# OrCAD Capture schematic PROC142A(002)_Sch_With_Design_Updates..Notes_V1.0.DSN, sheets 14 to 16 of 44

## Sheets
14 13. CURRENT MONITORING DEVICES: size C; title: CURRENT MONITORING DEVICES
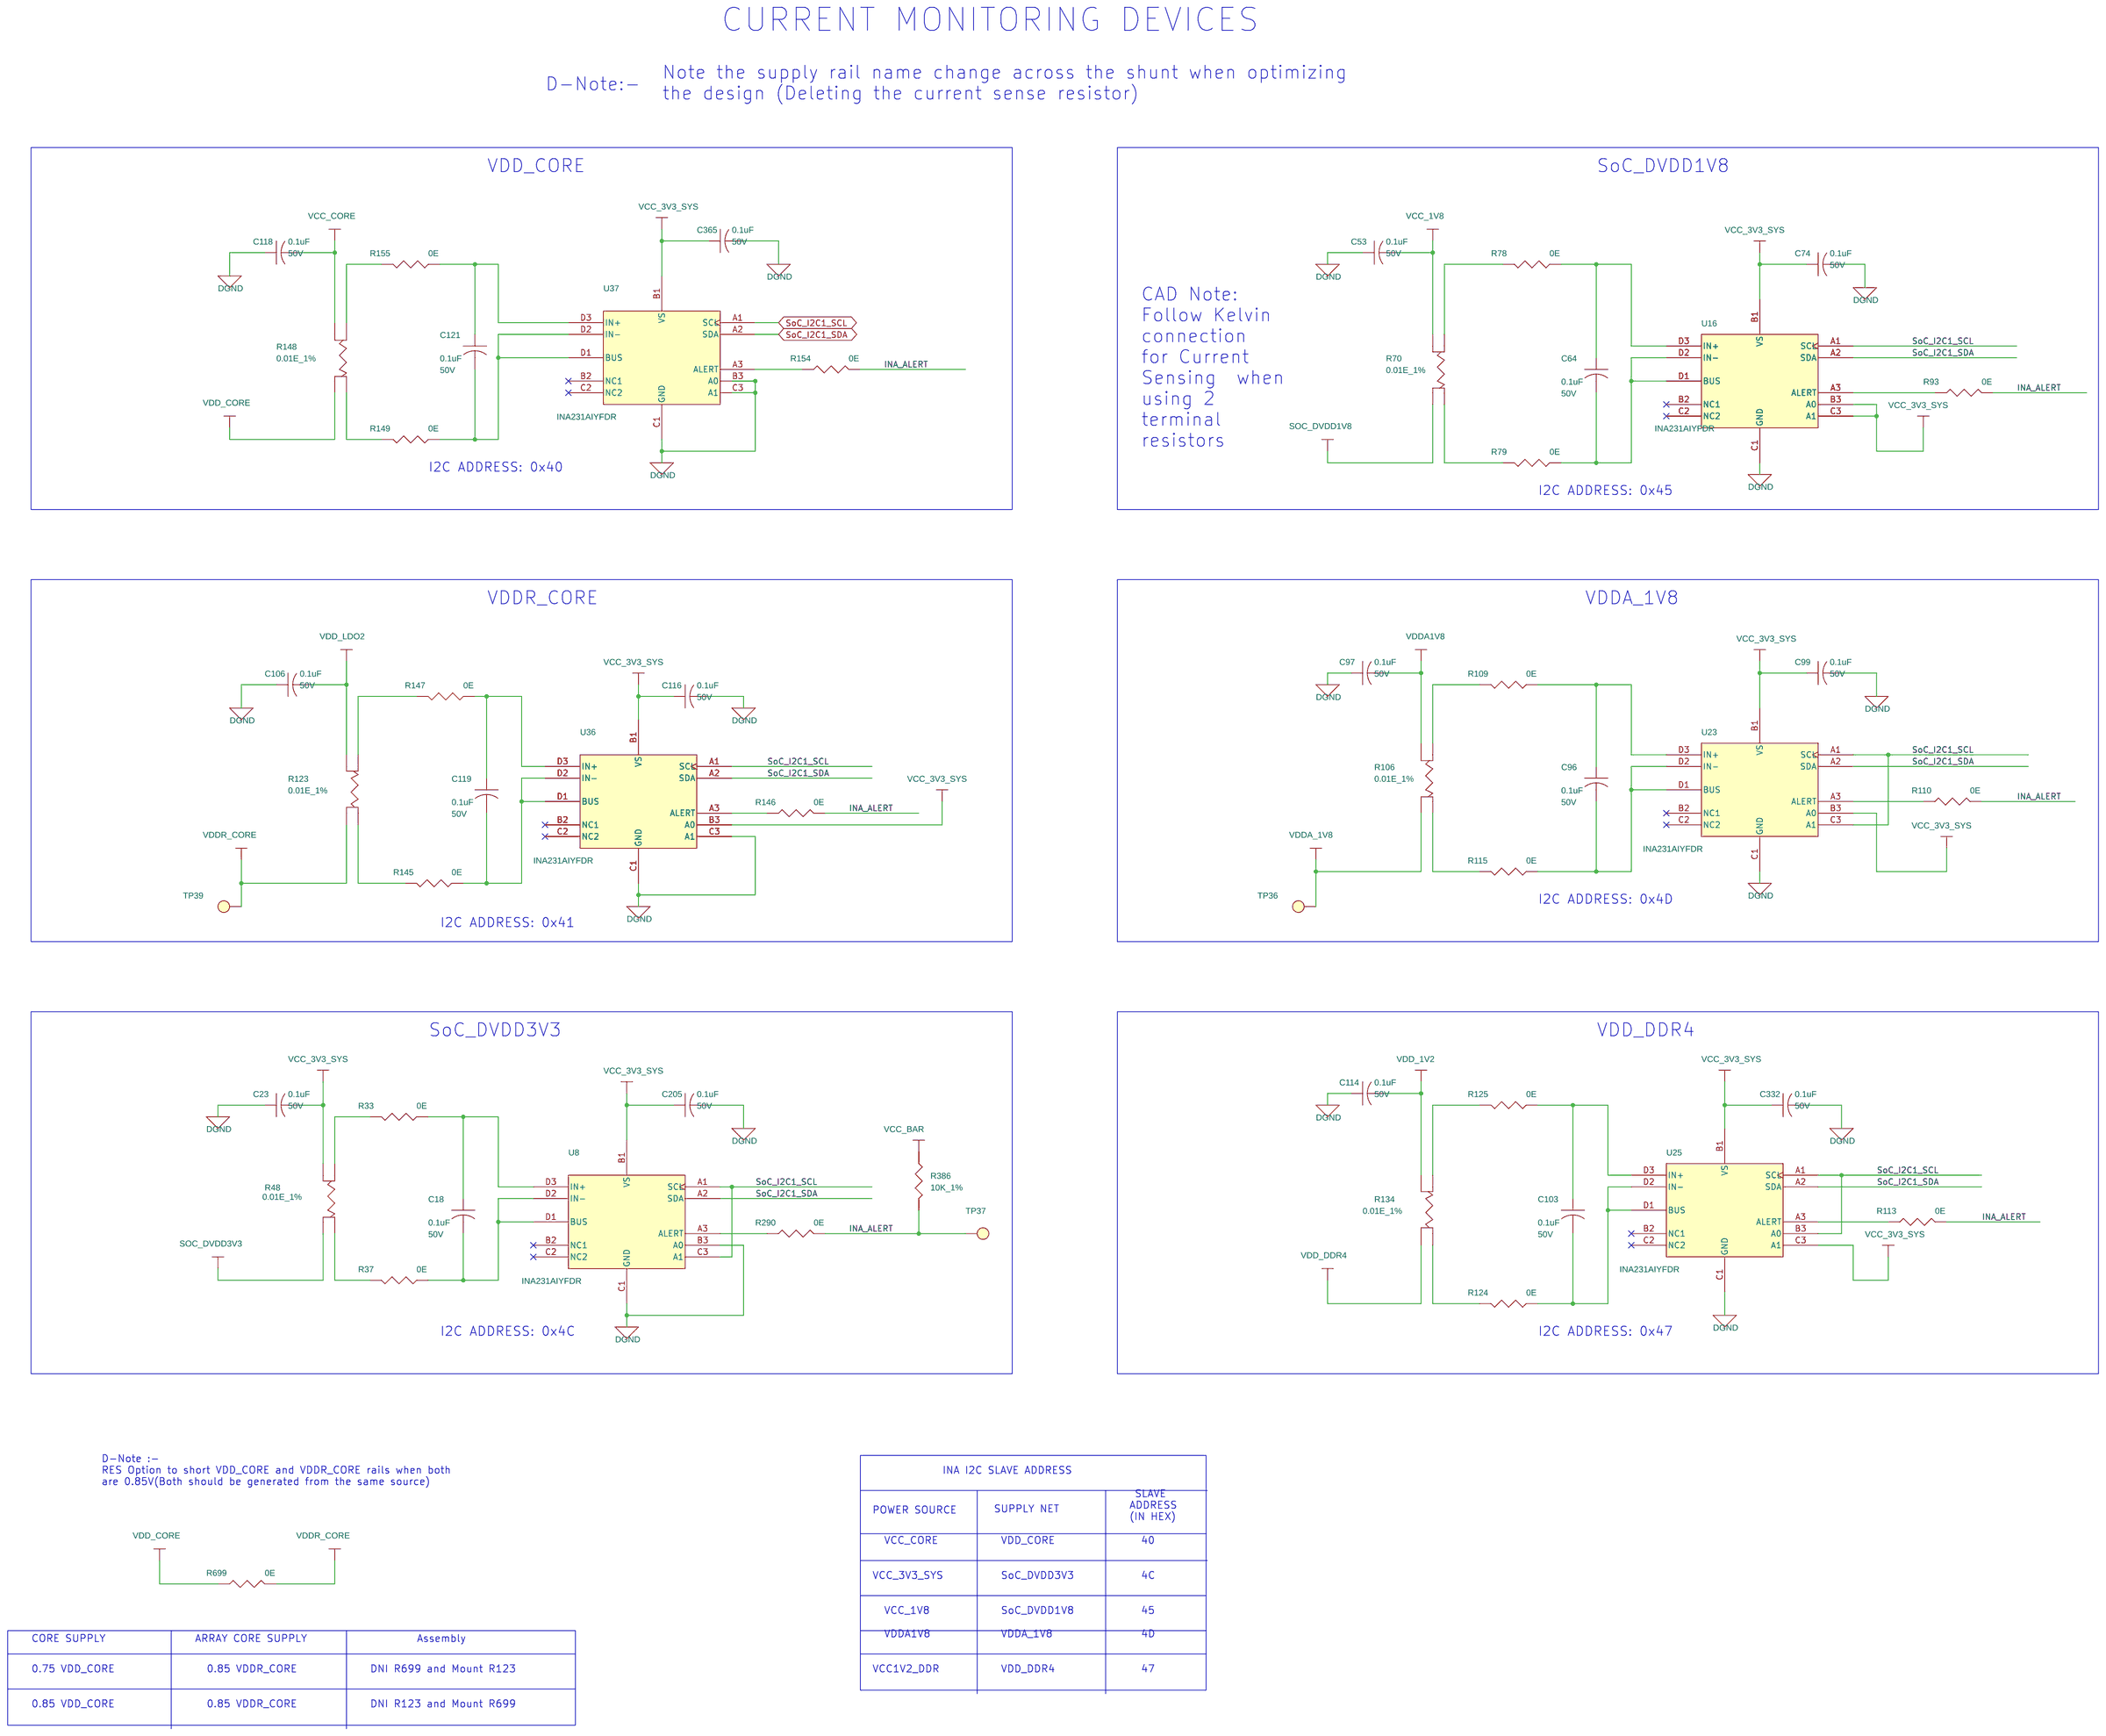
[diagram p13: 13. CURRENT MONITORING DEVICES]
15 14. SOC POWER: size C; title: SOC POWER
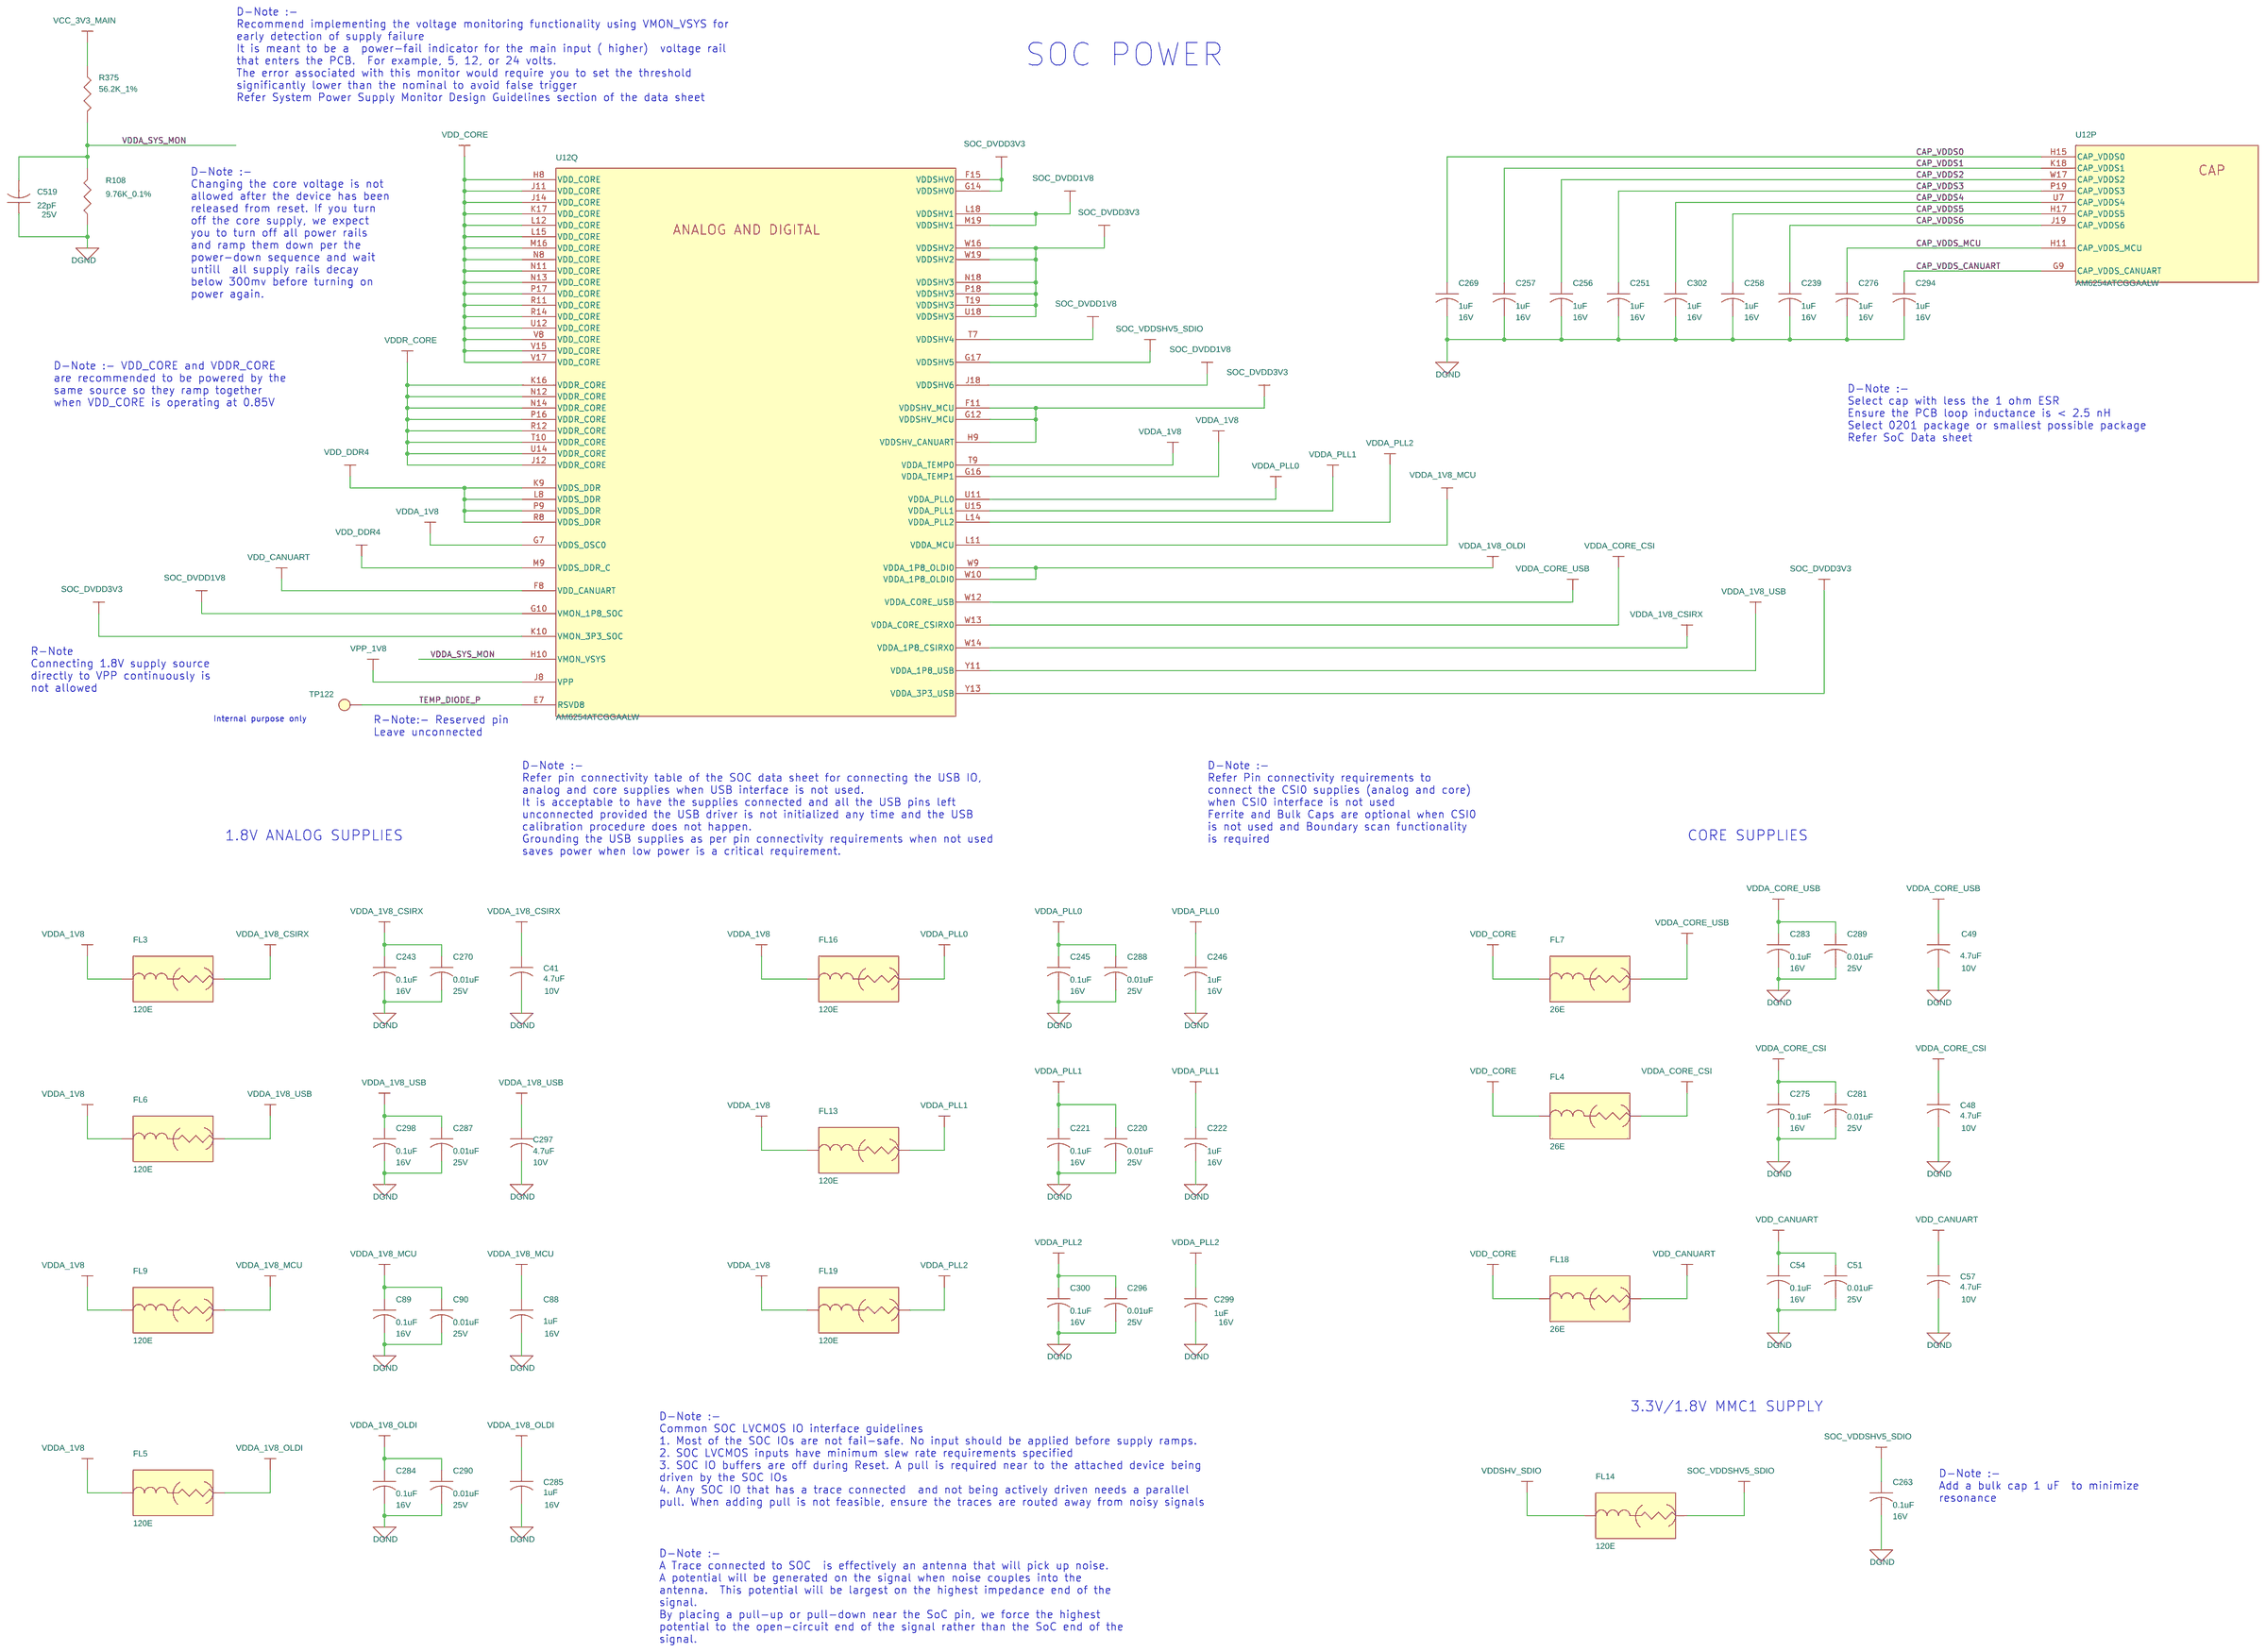
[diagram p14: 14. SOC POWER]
16 15. SOC POWER CAPS: size C; title: SOC POWER CAPS & SOC VSS
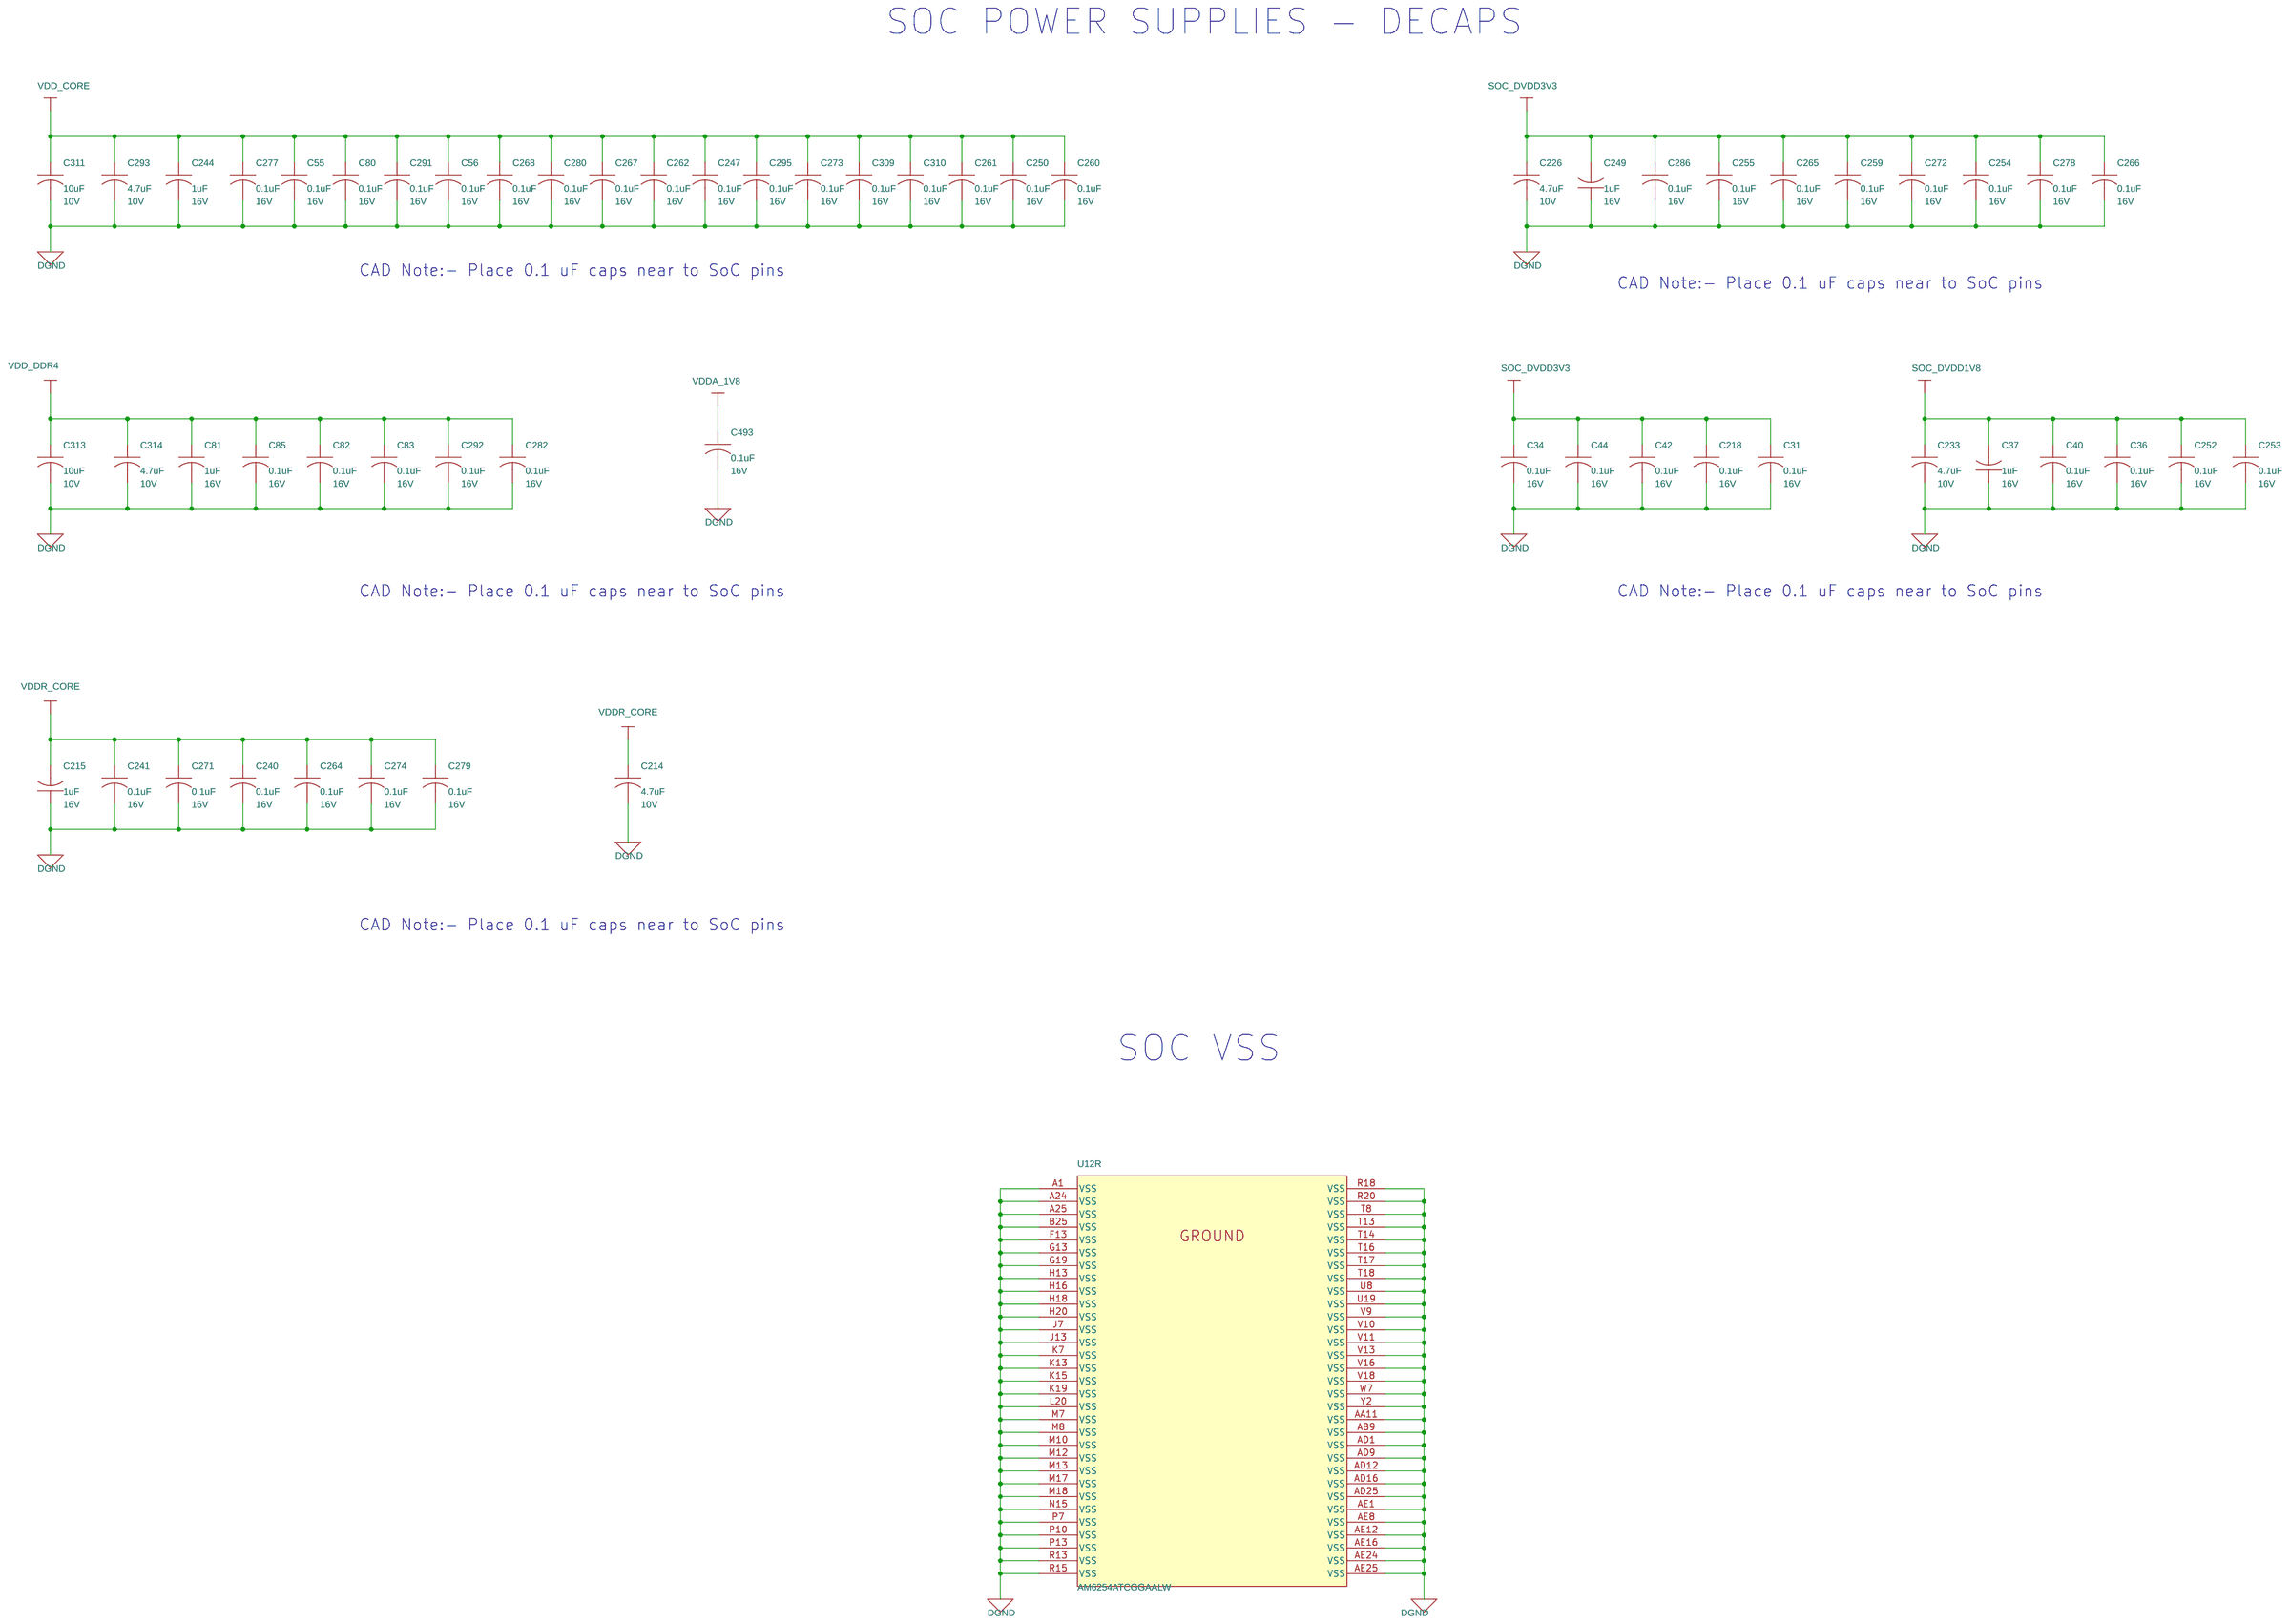
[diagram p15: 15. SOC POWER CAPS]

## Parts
sheet 13. CURRENT MONITORING DEVICES
C18  0.1uF  [CAP0402_0-75]
C23  0.1uF  [CAP0402_0-75]
C53  0.1uF  [CAP0402_0-75]
C64  0.1uF  [CAP0402_0-75]
C74  0.1uF  [CAP0402_0-75]
C96  0.1uF  [CAP0402_0-75]
C97  0.1uF  [CAP0402_0-75]
C99  0.1uF  [CAP0402_0-75]
C103  0.1uF  [CAP0402_0-75]
C106  0.1uF  [CAP0402_0-75]
C114  0.1uF  [CAP0402_0-75]
C116  0.1uF  [CAP0402_0-75]
C118  0.1uF  [CAP0402_0-75]
C119  0.1uF  [CAP0402_0-75]
C121  0.1uF  [CAP0402_0-75]
C205  0.1uF  [CAP0402_0-75]
C332  0.1uF  [CAP0402_0-75]
C365  0.1uF  [CAP0402_0-75]
R33  0E  [RES0402_0-5]
R37  0E  [RES0402_0-5]
R48  0.01E_1%  [RES_KRL3216T4_1206-4_0-7]
R70  0.01E_1%  [RES_KRL3216T4_1206-4_0-7]
R78  0E  [RES0402_0-5]
R79  0E  [RES0402_0-5]
R93  0E  [RES0402_0-5]
R106  0.01E_1%  [RES_KRL3216T4_1206-4_0-7]
R109  0E  [RES0402_0-5]
R110  0E  [RES0402_0-5]
R113  0E  [RES0402_0-5]
R115  0E  [RES0402_0-5]
R123  0.01E_1%  [RES_KRL3216T4_1206-4_0-7]
R124  0E  [RES0402_0-5]
R125  0E  [RES0402_0-5]
R134  0.01E_1%  [RES_KRL3216T4_1206-4_0-7]
R145  0E  [RES0402_0-5]
R146  0E  [RES0402_0-5]
R147  0E  [RES0402_0-5]
R148  0.01E_1%  [RES_KRL3216T4_1206-4_0-7]
R149  0E  [RES0402_0-5]
R154  0E  [RES0402_0-5]
R155  0E  [RES0402_0-5]
R290  0E  [RES0402_0-5]
R386  10K_1%  [RES0201_0-5]
R699  0E  [RES0805_0-75]
TP36  TP20_SMD  [TP20_SMD]
TP37  TP20_SMD  [TP20_SMD]
TP39  TP20_SMD  [TP20_SMD]
U8  INA231AIYFDR  [DSBGA12_15-74_60X70_0-4]
U16  INA231AIYFDR  [DSBGA12_15-74_60X70_0-4]
U23  INA231AIYFDR  [DSBGA12_15-74_60X70_0-4]
U25  INA231AIYFDR  [DSBGA12_15-74_60X70_0-4]
U36  INA231AIYFDR  [DSBGA12_15-74_60X70_0-4]
U37  INA231AIYFDR  [DSBGA12_15-74_60X70_0-4]
sheet 14. SOC POWER
C41  4.7uF  [CAP0402_0-75]
C48  4.7uF  [CAP0402_0-75]
C49  4.7uF  [CAP0402_0-75]
C51  0.01uF  [CAP0201_0-5]
C54  0.1uF  [CAP0201_0-5]
C57  4.7uF  [CAP0402_0-75]
C88  1uF  [CAP0201_0-5]
C89  0.1uF  [CAP0201_0-5]
C90  0.01uF  [CAP0201_0-5]
C220  0.01uF  [CAP0201_0-5]
C221  0.1uF  [CAP0201_0-5]
C222  1uF  [CAP0201_0-5]
C239  1uF  [CAP0201_0-5]
C243  0.1uF  [CAP0201_0-5]
C245  0.1uF  [CAP0201_0-5]
C246  1uF  [CAP0201_0-5]
C251  1uF  [CAP0201_0-5]
C256  1uF  [CAP0201_0-5]
C257  1uF  [CAP0201_0-5]
C258  1uF  [CAP0201_0-5]
C263  0.1uF  [CAP0201_0-5]
C269  1uF  [CAP0201_0-5]
C270  0.01uF  [CAP0201_0-5]
C275  0.1uF  [CAP0201_0-5]
C276  1uF  [CAP0201_0-5]
C281  0.01uF  [CAP0201_0-5]
C283  0.1uF  [CAP0201_0-5]
C284  0.1uF  [CAP0201_0-5]
C285  1uF  [CAP0201_0-5]
C287  0.01uF  [CAP0201_0-5]
C288  0.01uF  [CAP0201_0-5]
C289  0.01uF  [CAP0201_0-5]
C290  0.01uF  [CAP0201_0-5]
C294  1uF  [CAP0201_0-5]
C296  0.01uF  [CAP0201_0-5]
C297  4.7uF  [CAP0402_0-75]
C298  0.1uF  [CAP0201_0-5]
C299  1uF  [CAP0201_0-5]
C300  0.1uF  [CAP0201_0-5]
C302  1uF  [CAP0201_0-5]
C519  22pF  [CAP0201_0-5]
FL3  120E  [EMIFIL_BLM15A_0402_0-6]
FL4  26E  [EMIFIL_BLM18K_0603_0-7]
FL5  120E  [EMIFIL_BLM15A_0402_0-6]
FL6  120E  [EMIFIL_BLM15A_0402_0-6]
FL7  26E  [EMIFIL_BLM18K_0603_0-7]
FL9  120E  [EMIFIL_BLM15A_0402_0-6]
FL13  120E  [EMIFIL_BLM15A_0402_0-6]
FL14  120E  [EMIFIL_BLM15A_0402_0-6]
FL16  120E  [EMIFIL_BLM15A_0402_0-6]
FL18  26E  [EMIFIL_BLM18K_0603_0-7]
FL19  120E  [EMIFIL_BLM15A_0402_0-6]
R108  9.76K_0.1%  [RES0402_0-5]
R375  56.2K_1%  [RES0402_0-5]
TP122  TP20_SMD  [TP20_SMD]
sheet 15. SOC POWER CAPS
C31  0.1uF  [CAP0201_0-5]
C34  0.1uF  [CAP0201_0-5]
C36  0.1uF  [CAP0201_0-5]
C37  1uF  [CAP0201_0-5]
C40  0.1uF  [CAP0201_0-5]
C42  0.1uF  [CAP0201_0-5]
C44  0.1uF  [CAP0201_0-5]
C55  0.1uF  [CAP0201_0-5]
C56  0.1uF  [CAP0201_0-5]
C80  0.1uF  [CAP0201_0-5]
C81  1uF  [CAP0201_0-5]
C82  0.1uF  [CAP0201_0-5]
C83  0.1uF  [CAP0201_0-5]
C85  0.1uF  [CAP0201_0-5]
C214  4.7uF  [CAP0402_0-75]
C215  1uF  [CAP0201_0-5]
C218  0.1uF  [CAP0201_0-5]
C226  4.7uF  [CAP0402_0-75]
C233  4.7uF  [CAP0402_0-75]
C240  0.1uF  [CAP0201_0-5]
C241  0.1uF  [CAP0201_0-5]
C244  1uF  [CAP0201_0-5]
C247  0.1uF  [CAP0201_0-5]
C249  1uF  [CAP0201_0-5]
C250  0.1uF  [CAP0201_0-5]
C252  0.1uF  [CAP0201_0-5]
C253  0.1uF  [CAP0201_0-5]
C254  0.1uF  [CAP0201_0-5]
C255  0.1uF  [CAP0201_0-5]
C259  0.1uF  [CAP0201_0-5]
C260  0.1uF  [CAP0201_0-5]
C261  0.1uF  [CAP0201_0-5]
C262  0.1uF  [CAP0201_0-5]
C264  0.1uF  [CAP0201_0-5]
C265  0.1uF  [CAP0201_0-5]
C266  0.1uF  [CAP0201_0-5]
C267  0.1uF  [CAP0201_0-5]
C268  0.1uF  [CAP0201_0-5]
C271  0.1uF  [CAP0201_0-5]
C272  0.1uF  [CAP0201_0-5]
C273  0.1uF  [CAP0201_0-5]
C274  0.1uF  [CAP0201_0-5]
C277  0.1uF  [CAP0201_0-5]
C278  0.1uF  [CAP0201_0-5]
C279  0.1uF  [CAP0201_0-5]
C280  0.1uF  [CAP0201_0-5]
C282  0.1uF  [CAP0201_0-5]
C286  0.1uF  [CAP0201_0-5]
C291  0.1uF  [CAP0201_0-5]
C292  0.1uF  [CAP0201_0-5]
C293  4.7uF  [CAP0402_0-75]
C295  0.1uF  [CAP0201_0-5]
C309  0.1uF  [CAP0201_0-5]
C310  0.1uF  [CAP0201_0-5]
C311  10uF  [CAP0402_0-75]
C313  10uF  [CAP0402_0-75]
C314  4.7uF  [CAP0402_0-75]
C493  0.1uF  [CAP0201_0-5]
sheet 42. OSCILLATOR
U12  AM6254ATCGGAALW  [BGA425_19-68_510X510_0-7]  (sections A,B,C,D,E,F,G,H,I,J,K,L,M,N,O,P,Q,R)

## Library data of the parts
C18 C23 C53 C64 C74 C96 C97 C99 C103 C106 C114 C116 C118 C119 C121 C205 C332 C365 = CAP: CAP CERAMIC 0.1uF 50V 10% X7R 0402; Alt_Mfr_name: YAGEO AMERICA; Alt_Mfr_part_number: CC0402KRX5R8BB104; Chkd/date: MANIRAJA/261020; Crtd /date: ALVY/211020; Custom_Duty: 15%; Customs_HS_Code: 85322990; Distributor_name: DIGIKEY; Distributor_part_number: 490-10700-1-ND; Footprint Path: Y:\MIS_DATABASE\Library\ALTIUM_TOOL\PCB_FOOTPRINTS\Altium_Footprint_Lib.PcbLib; Height: 0.55MM; Library Path: Y:\MIS_DATABASE\Library\ALTIUM_TOOL\SCHEMATICS_PARTS\MS_DISCRETE_Library.schlib; Mfr_name: MURATA; Mfr_part_number: GRM155R71H104KE14D; Mistral Part No: 120011100014-R; Package: 0402; Part_type: CAPACITORS\CERAMIC; Project: J7_CP; RoHS: RoHS; Temperature: -55°C+125°C; Tolerance: 10%; Voltage: 50V; Wattage: NA; Weight: 3.1mg; Datasheet: Y:\MIS_DATABASE\DATASHEETS\CAPACITORS\GRM155R71H104KE14.PDF
R33 R37 R78 R79 R93 R109 R110 R113 R115 R124 R125 R145-R147 R149 R154 R155 R290 = RESISTOR: RES 0E 1/16W JUMPER 0402; Chkd/date: VASANTHA/201216; Crtd /date: MUDDU/190810; Custom_Duty: 15%; Customs_HS_Code: 85332119; Distributor_name: DIGIKEY; Distributor_part_number: 541-0.0JCT-ND; Footprint Path: Y:\MIS_DATABASE\Library\ALTIUM_TOOL\PCB_FOOTPRINTS\Altium_Footprint_Lib.PcbLib; Height: 0.40MM; Library Path: Y:\MIS_DATABASE\Library\ALTIUM_TOOL\SCHEMATICS_PARTS\MS_DISCRETE_Library.schlib; Mfr_name: VISHAY; Mfr_part_number: CRCW04020000Z0ED; Mistral Part No: 110010080019-R; Package: 0402; Part_type: RESISTORS\FIXED; Project: PB_BUGBASE; RoHS: RoHS; Temperature: -55°C+155°C; Tolerance: NA; Voltage: NA; Wattage: 1/16W; Weight: 0.65mg; Datasheet: Y:\MIS_DATABASE\DATASHEETS\RESISTORS\CRCW0603.PDF
R48 R70 R106 R123 R134 R148 = RESISTOR-4TERM: RES 0.01E 1W 1% 1206-4; Chkd/date: MANIRAJA/060318; Crtd /date: MANIRAJA/060318; Custom_Duty: 15%; Customs_HS_Code: 85332119; Distributor_name: DIGIKEY; Distributor_part_number: 408-1974-1-ND; Footprint Path: Y:\MIS_DATABASE\Library\ALTIUM_TOOL\PCB_FOOTPRINTS\Altium_Footprint_Lib.PcbLib; Height: 0.70MM; Library Path: Y:\MIS_DATABASE\Library\ALTIUM_TOOL\SCHEMATICS_PARTS\MS_DISCRETE_Library.schlib; Mfr_name: SUSUMU; Mfr_part_number: KRL3216T4A-M-R010-F-T1; Mistral Part No: 110018030003-R; Package: 1206-4; Part_type: RESISTORS\FIXED; Project: GRACO SMART MODULE; RoHS: RoHS; Temperature: -55°C+155°C; Tolerance: 1%; Voltage: NA; Wattage: 1W; Weight: 16.2mg; Datasheet: Y:\MIS_DATABASE\DATASHEETS\RESISTORS\KRL-SERIES.PDF
R386 = RESISTOR: RES 10K 1/20W 1% 0201; Chkd/date: VASANTHA/270117; Crtd /date: MANIRAJA/270117; Custom_Duty: 15%; Customs_HS_Code: 85332119; Distributor_name: DIGIKEY; Distributor_part_number: 311-10.0KMCT-ND; Footprint Path: Y:\MIS_DATABASE\Library\ALTIUM_TOOL\PCB_FOOTPRINTS\Altium_Footprint_Lib.PcbLib; Height: 0.26MM; Library Path: Y:\MIS_DATABASE\Library\ALTIUM_TOOL\SCHEMATICS_PARTS\MS_DISCRETE_Library.schlib; Mfr_name: YAGEO AMERICA; Mfr_part_number: RC0201FR-0710KL; Mistral Part No: 110011040018-R; Package: 0201; Part_type: RESISTORS\FIXED; Project: GOLDEN-I LITE; RoHS: RoHS; Temperature: -55°C+125°C; Tolerance: 1%; Voltage: NA; Wattage: 1/20W; Weight: 0.17mg; Datasheet: Y:\MIS_DATABASE\DATASHEETS\RESISTORS\RCXXXXL-SER_MAR18.PDF
R699 = RESISTOR: RES 0E 1/8W 5% 0805; Chkd/date: VASANTHA/130416; Crtd /date: JEBRAN/020316; Custom_Duty: 15%; Customs_HS_Code: 85332119; Distributor_name: DIGIKEY; Distributor_part_number: 311-0.0ARCT-ND; Footprint Path: Y:\MIS_DATABASE\Library\ALTIUM_TOOL\PCB_FOOTPRINTS\Altium_Footprint_Lib.PcbLib; Height: 0.60MM; Library Path: Y:\MIS_DATABASE\Library\ALTIUM_TOOL\SCHEMATICS_PARTS\MS_DISCRETE_Library.schlib; Mfr_name: YAGEO AMERICA; Mfr_part_number: RC0805JR-070RL; Mistral Part No: 110009030074-R; Package: 0805; Part_type: RESISTORS\FIXED; Project: ZK_BIOMETRIC; RoHS: RoHS; Temperature: -55°C+155°C; Tolerance: 5%; Voltage: NA; Wattage: 1/8W; Weight: 5.5mg; Datasheet: Y:\MIS_DATABASE\DATASHEETS\RESISTORS\RCXXXXL-SER_MAR18.PDF
TP36 TP37 TP39 TP122 = TESTPOINT: TESTPOINT CIR 20 SMD; Chkd/date: SHREESHAIL/171006; Crtd /date: MAZHAR/171006; Custom_Duty: NA; Customs_HS_Code: NA; Distributor_name: NA; Distributor_part_number: NA; Footprint Path: Y:\MIS_DATABASE\Library\ALTIUM_TOOL\PCB_FOOTPRINTS\Altium_Footprint_Lib.PcbLib; Height: NA; Library Path: Y:\MIS_DATABASE\Library\ALTIUM_TOOL\SCHEMATICS_PARTS\MS_DISCRETE_Library.schlib; MECHANICAL 3D STEP FILE: NA; Mfr_name: LOCAL; Mistral Part No: NA; Package: SMD; Project: BT MODULE_CSRBC04; RoHS: NA; Temperature: NA; Tolerance: NA; Voltage: NA; Wattage: NA; Weight: NA; Datasheet: NA
U8 U16 U23 U25 U36 U37 = INA231_DSBGA12: IC HIGH OR LOW SIDE MEASUREMENT BI-DIR CURRENT AND POWER MONITOR WITH 1.8V I2C INTERFACE DSBGA12; Chkd/date: MANIRAJA/250821; Crtd /date: ALVY/250821; Custom_Duty: 15%; Customs_HS_Code: 85423100; Distributor_name: DIGIKEY; Distributor_part_number: 296-49645-1-ND; Footprint Path: Y:\MIS_DATABASE\Library\ALTIUM_TOOL\PCB_FOOTPRINTS\Altium_Footprint_Lib.PcbLib; Height: 0.40MM; Library Path: Y:\MIS_DATABASE\Library\ALTIUM_TOOL\SCHEMATICS_PARTS\MS_MISCPOWER_Library.schlib; Mfr_name: TEXAS INSTRUMENTS; Mistral Part No: 142021080022-R; Package: DSBGA12; Part_type: ICS\POWER\MANAGEMENT; Project: TI_AM62x SVB_BRD; RoHS: RoHS; Temperature: -40°C+125°C; Tolerance: NA; Voltage: NA; Wattage: NA; Weight: 200mg; Datasheet: Y:\MIS_DATABASE\DATASHEETS\ICS\POWER\INA231XXX.PDF
C41 C48 C49 C57 C214 C226 C233 C293 C297 C314 = CAP: CAP CERAMIC 4.7uF 10V 20% X5R 0402; Chkd/date: MANIRAJA/110718; Crtd /date: ALVY/110718; Custom_Duty: 15%; Customs_HS_Code: 85322990; Distributor_name: DIGIKEY; Distributor_part_number: 490-14306-1-ND; Footprint Path: Y:\MIS_DATABASE\Library\ALTIUM_TOOL\PCB_FOOTPRINTS\Altium_Footprint_Lib.PcbLib; Height: 0.65MM; Library Path: Y:\MIS_DATABASE\Library\ALTIUM_TOOL\SCHEMATICS_PARTS\MS_DISCRETE_Library.schlib; Mfr_name: MURATA; Mfr_part_number: GRM155R61A475MEAAD; Mistral Part No: 120012060002-R; Package: 0402; Part_type: CAPACITORS\CERAMIC; Project: TI_J7SVB_PCIE_ADD-ON-CARD; RoHS: RoHS; Temperature: -55°C+85°C; Tolerance: 20%; Voltage: 10V; Wattage: NA; Weight: 14mg; Datasheet: Y:\MIS_DATABASE\DATASHEETS\CAPACITORS\GRM155R61A475MEAAD.PDF
C51 C90 C220 C270 C281 C287-C290 C296 = CAP: CAP CERAMIC 0.01uF 25V 10% X5R 0201; Chkd/date: MANIRAJA/230118; Crtd /date: MANIRAJA/230118; Custom_Duty: 15%; Customs_HS_Code: 85322990; Distributor_name: DIGIKEY; Distributor_part_number: GRM033R61E103KA12J-ND; Footprint Path: Y:\MIS_DATABASE\Library\ALTIUM_TOOL\PCB_FOOTPRINTS\Altium_Footprint_Lib.PcbLib; Height: 0.33MM; Library Path: Y:\MIS_DATABASE\Library\ALTIUM_TOOL\SCHEMATICS_PARTS\MS_DISCRETE_Library.schlib; Mfr_name: MURATA; Mfr_part_number: GRM033R61E103KA12J; Mistral Part No: 120018010007-R; Package: 0201; Part_type: CAPACITORS\CERAMIC; Project: TI_MAXIE_CPB; RoHS: RoHS; Temperature: -55°C+85°C; Tolerance: 10%; Voltage: 25V; Wattage: NA; Weight: 0.33mg; Datasheet: Y:\MIS_DATABASE\DATASHEETS\CAPACITORS\GRM033R61E103KA12.PDF
C31 C34 C36 C40 C42 C44 C54-C56 C80 C82 C83 C85 C89 C218 C221 C240 C241 C243 C245 C247 C250 C252-C255 C259-C268 C271-C275 C277-C280 C282-C284 C286 C291 C292 C295 C298 C300 C309 C310 C493 = CAP: CAP CERAMIC 0.1uF 16V 10% X5R 0201; Chkd/date: MANIRAJA/230118; Crtd /date: MANIRAJA/230118; Custom_Duty: 15%; Customs_HS_Code: 85322990; Distributor_name: DIGIKEY; Distributor_part_number: 490-14305-1-ND; Footprint Path: Y:\MIS_DATABASE\Library\ALTIUM_TOOL\PCB_FOOTPRINTS\Altium_Footprint_Lib.PcbLib; Height: 0.33MM; Library Path: Y:\MIS_DATABASE\Library\ALTIUM_TOOL\SCHEMATICS_PARTS\MS_DISCRETE_Library.schlib; Mfr_name: MURATA; Mfr_part_number: GRM033R61C104KE14D; Mistral Part No: 120009030072-R; Package: 0201; Part_type: CAPACITORS\CERAMIC; Project: TI_MAXIE_CPB; RoHS: RoHS; Temperature: -55°C+85°C; Tolerance: 10%; Voltage: 16V; Wattage: NA; Weight: 0.33mg; Datasheet: Y:\MIS_DATABASE\DATASHEETS\CAPACITORS\GRM033R61C104KE14.PDF
C37 C81 C88 C215 C222 C239 C244 C246 C249 C251 C256-C258 C269 C276 C285 C294 C299 C302 = CAP: CAP CERAMIC 1uF 16V 20% X5R 0201; Chkd/date: MANIRAJA/300520; Crtd /date: ALVY/260520; Custom_Duty: 15%; Customs_HS_Code: 85322990; Distributor_name: DIGIKEY; Distributor_part_number: 490-18654-1-ND; Footprint Path: Y:\MIS_DATABASE\Library\ALTIUM_TOOL\PCB_FOOTPRINTS\Altium_Footprint_Lib.PcbLib; Height: 0.39MM; Library Path: Y:\MIS_DATABASE\Library\ALTIUM_TOOL\SCHEMATICS_PARTS\MS_DISCRETE_Library.schlib; Mfr_name: MURATA; Mfr_part_number: GRM033R61C105ME15D; Mistral Part No: 120018090038-R; Package: 0201; Part_type: CAPACITORS\CERAMIC; Project: QCS610_NANOSOM; RoHS: RoHS; Temperature: -55°C+85°C; Tolerance: 20%; Voltage: 16V; Wattage: NA; Weight: 0.33mg; Datasheet: Y:\MIS_DATABASE\DATASHEETS\CAPACITORS\GRM033R61C105ME15.PDF
C519 = CAP: CAP CERAMIC 22pF 25V 1% C0G(NP0) 0201; Chkd/date: MANIRAJA/270721; Crtd /date: ALVY/260721; Custom_Duty: 15%; Customs_HS_Code: 85322990; Distributor_name: DIGIKEY; Distributor_part_number: 490-14545-1-ND; Footprint Path: Y:\MIS_DATABASE\Library\ALTIUM_TOOL\PCB_FOOTPRINTS\Altium_Footprint_Lib.PcbLib; Height: 0.33MM; Library Path: Y:\MIS_DATABASE\Library\ALTIUM_TOOL\SCHEMATICS_PARTS\MS_DISCRETE_Library.schlib; Mfr_name: MURATA; Mfr_part_number: GRM0335C1E220FA01D; Mistral Part No: 120021070019-R; Package: 0201; Part_type: CAPACITORS\CERAMIC; Project: TI_AM335x SK_BRD; RoHS: RoHS; Temperature: -55°C+125°C; Tolerance: 1%; Voltage: 25V; Wattage: NA; Weight: 0.33mg; Datasheet: Y:\MIS_DATABASE\DATASHEETS\CAPACITORS\GRM0335C1E220FA01.PDF
FL3 FL5 FL6 FL9 FL13 FL14 FL16 FL19 = EMIFILTER_IND: IND FERRITE BEAD CHIP 120E 2A 0402; Chkd/date: NAVEED/241114; Crtd /date: USMAN/170613; Custom_Duty: 24%; Customs_HS_Code: 85369090; Distributor_name: DIGIKEY; Distributor_part_number: 490-9656-1-ND; Footprint Path: Y:\MIS_DATABASE\Library\ALTIUM_TOOL\PCB_FOOTPRINTS\Altium_Footprint_Lib.PcbLib; Height: 0.55MM; Library Path: Y:\MIS_DATABASE\Library\ALTIUM_TOOL\SCHEMATICS_PARTS\MS_FILTER_Library.schlib; Mfr_name: MURATA; Mfr_part_number: BLM15PX121SN1D; Mistral Part No: 130013060022-R; Package: 0402; Part_type: INDUCTOR; Project: GEN_3-8; RoHS: RoHS; Temperature: -55°C+125°C; Tolerance: 25%; Voltage: NA; Wattage: NA; Weight: 1mg; Datasheet: Y:\MIS_DATABASE\DATASHEETS\DISCRETES\INDUCTORS\BLM15-SN1-SER.PDF
FL4 FL7 FL18 = EMIFILTER_IND: FERRITE CHIP 26E 6A 0603; Chkd/date: NAVEED/190115; Crtd /date: USMAN/251013; Custom_Duty: 15%; Customs_HS_Code: 85412900; Distributor_name: DIGIKEY; Distributor_part_number: 490-3995-1-ND; Height: 0.65MM; Mfr_name: MURATA; Mfr_part_number: BLM18SG260TN1D; Mistral Part No: 130013100028-R; Package: 0603; Part_type: FILTER; Project: DTRM_SBAND; RoHS: RoHS; Temperature: -55°C+125°C; Tolerance: 25%; Voltage: NA; Wattage: NA; Weight: 2mg; Datasheet: Y:\MIS_DATABASE\DATASHEETS\DISCRETES\INDUCTORS\BLM18K-SERIES.PDF
R108 = RESISTOR: RES 9.76K 1/16W 0.1% 0402; Chkd/date: MANIRAJA/190419; Crtd /date: MANIRAJA/190419; Custom_Duty: 15%; Customs_HS_Code: 85332119; Distributor_name: DIGIKEY; Distributor_part_number: P9.76KDCCT-ND; Footprint Path: Y:\MIS_DATABASE\Library\ALTIUM_TOOL\PCB_FOOTPRINTS\Altium_Footprint_Lib.PcbLib; Height: 0.40MM; Library Path: Y:\MIS_DATABASE\Library\ALTIUM_TOOL\SCHEMATICS_PARTS\MS_DISCRETE_Library.schlib; Mfr_name: PANASONIC-ECG; Mfr_part_number: ERA-2AEB9761X; Mistral Part No: 110019040291-R; Package: 0402; Part_type: RESISTORS\FIXED; Project: TI_J7ES_EVM_FUSION2_SER_CAP; RoHS: RoHS; Temperature: -55°C+155°C; Tolerance: 0.1%; Voltage: NA; Wattage: 1/16W; Weight: 0.6mg; Datasheet: Y:\MIS_DATABASE\DATASHEETS\RESISTORS\ERA-1A.PDF
R375 = RESISTOR: RES 56.2K 1/16W 1% 0402; Chkd/date: SHREESHAIL/240507; Crtd /date: MAZHAR/010806; Custom_Duty: 15%; Customs_HS_Code: 85332119; Distributor_name: NA; Distributor_part_number: NA; Footprint Path: Y:\MIS_DATABASE\Library\ALTIUM_TOOL\PCB_FOOTPRINTS\Altium_Footprint_Lib.PcbLib; Height: 0.40MM; Library Path: Y:\MIS_DATABASE\Library\ALTIUM_TOOL\SCHEMATICS_PARTS\MS_DISCRETE_Library.schlib; Mfr_name: YAGEO AMERICA; Mfr_part_number: 9C04021A5622FLHF3; Mistral Part No: 110009030982; Package: 0402; Part_type: RESISTORS\FIXED; Project: POWERBOX; RoHS: NA; Temperature: -55°C+155°C; Tolerance: 1%; Voltage: NA; Wattage: 1/16W; Weight: 0.58mg; Datasheet: Y:\MIS_DATABASE\DATASHEETS\RESISTORS\9C_SERIES.PDF
C311 C313 = CAP: CAP CERAMIC 10uF 10V 20% X5R 0402; Chkd/date: MANIRAJA/300520; Crtd /date: ALVY/260520; Custom_Duty: 15%; Customs_HS_Code: 85322990; Distributor_name: DIGIKEY; Distributor_part_number: 490-GRM155R61A106ME11DTR-ND; Footprint Path: Y:\MIS_DATABASE\Library\ALTIUM_TOOL\PCB_FOOTPRINTS\Altium_Footprint_Lib.PcbLib; Height: 0.55MM; Library Path: Y:\MIS_DATABASE\Library\ALTIUM_TOOL\SCHEMATICS_PARTS\MS_DISCRETE_Library.schlib; Mfr_name: MURATA; Mfr_part_number: GRM155R61A106ME11D; Mistral Part No: 120013110019-R; Package: 0402; Part_type: CAPACITORS\CERAMIC; Project: QCS610_NANOSOM; RoHS: RoHS; Temperature: -55°C+85°C; Tolerance: 20%; Voltage: 10V; Wattage: NA; Weight: 3.1mg; Datasheet: Y:\MIS_DATABASE\DATASHEETS\CAPACITORS\MURATA-GXX-SER_NOV17.PDF
U12 = AM62-EVM_BGA425: IC AM62 SoC MICROPROCESSOR BGA425; Chkd/date: ALVY/110621; Crtd /date: MANIRAJA/110621; Custom_Duty: 15%; Customs_HS_Code: 85423100; Distributor_name: NA; Distributor_part_number: NA; Footprint Path: Y:\MIS_DATABASE\Library\ALTIUM_TOOL\PCB_FOOTPRINTS\Altium_Footprint_Lib.PcbLib; Height: 0.65MM; Library Path: Y:\MIS_DATABASE\Library\ALTIUM_TOOL\SCHEMATICS_PARTS\MS_MICROPROCESSOR_Library.schlib; Mfr_name: TEXAS INSTRUMENTS; Mistral Part No: 141221060001; Package: BGA425; Part_type: ICS\DIGITAL\MICROPROCESSOR; Project: AM62_EVM_BRD; RoHS: NA; Temperature: NA; Tolerance: NA; Voltage: NA; Wattage: NA; Weight: NA; Datasheet: Y:\MIS_DATABASE\DATASHEETS\ICS\DIGITAL\MICROCONTROLLER\AM62-SoC_SVB.PDF

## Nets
DGND: C23.1 C31.2 C34.2 C36.2 C37.1 C40.2 C41.2 C42.2 C44.2 C48.2 C49.2 C51.2 C53.1 C54.2 C55.2 C56.2 C57.2 C74.2 C80.2 C81.2 C82.2 C83.2 C85.2 C88.2 C89.2 C90.2 C97.1 C99.2 C106.1 C114.1 C116.2 C118.1 C205.2 C214.2 C215.1 C218.2 C220.2 C221.2 C222.2 C226.2 C233.2 C239.2 C240.2 C241.2 C243.2 C244.2 C245.2 C246.2 C247.2 C249.1 C250.2 C251.2 C252.2 C253.2 C254.2 C255.2 C256.2 C257.2 C258.2 C259.2 C260.2 C261.2 C262.2 C263.2 C264.2 C265.2 C266.2 C267.2 C268.2 C269.2 C270.2 C271.2 C272.2 C273.2 C274.2 C275.2 C276.2 C277.2 C278.2 C279.2 C280.2 C281.2 C282.2 C283.2 C284.2 C285.2 C286.2 C287.2 C288.2 C289.2 C290.2 C291.2 C292.2 C293.2 C294.2 C295.2 C296.2 C297.2 C298.2 C299.2 C300.2 C302.2 C309.2 C310.2 C311.2 C313.2 C314.2 C332.2 C365.2 C493.2 C519.1 R108.2 U8.B3(A0) U8.C1(GND) U12.A1(VSS) U12.A24(VSS) U12.A25(VSS) U12.AA11(VSS) U12.AB9(VSS) U12.AD1(VSS) U12.AD9(VSS) U12.AD12(VSS) U12.AD16(VSS) U12.AD25(VSS) U12.AE1(VSS) U12.AE8(VSS) U12.AE12(VSS) U12.AE16(VSS) U12.AE24(VSS) U12.AE25(VSS) U12.B25(VSS) U12.F13(VSS) U12.G13(VSS) U12.G19(VSS) U12.H13(VSS) U12.H16(VSS) U12.H18(VSS) U12.H20(VSS) U12.J7(VSS) U12.J13(VSS) U12.K7(VSS) U12.K13(VSS) U12.K15(VSS) U12.K19(VSS) U12.L20(VSS) U12.M7(VSS) U12.M8(VSS) U12.M10(VSS) U12.M12(VSS) U12.M13(VSS) U12.M17(VSS) U12.M18(VSS) U12.N15(VSS) U12.P7(VSS) U12.P10(VSS) U12.P13(VSS) U12.R13(VSS) U12.R15(VSS) U12.R18(VSS) U12.R20(VSS) U12.T8(VSS) U12.T13(VSS) U12.T14(VSS) U12.T16(VSS) U12.T17(VSS) U12.T18(VSS) U12.U8(VSS) U12.U19(VSS) U12.V9(VSS) U12.V10(VSS) U12.V11(VSS) U12.V13(VSS) U12.V16(VSS) U12.V18(VSS) U12.W7(VSS) U12.Y2(VSS) U16.C1(GND) U23.C1(GND) U25.C1(GND) U36.C1(GND) U36.C3(A1) U37.B3(A0) U37.C1(GND) U37.C3(A1) ; also on sheet 1 10 11 12 13 17 18 19 20 21 22 23 24 25 26 27 28 29 30 31 32 33 34 35 36 37 38 39 40 41 42 43
VCC_1V8: C53.2 R70.2 ; also on sheet 12 13 18 19 21 25 34 37 39 40 42
VCC_3V3_MAIN: R375.1 ; also on sheet 12 13 26
VCC_3V3_SYS: C23.2 C74.1 C99.1 C116.1 C205.1 C332.1 C365.1 R48.2 R386.2 U8.B1(VS) U16.B1(VS) U16.B3(A0) U16.C3(A1) U23.B1(VS) U23.B3(A0) U25.B1(VS) U25.C3(A1) U36.B1(VS) U36.B3(A0) U37.B1(VS) ; also on sheet 10 12 13 18 19 20 22 23 24 25 26 27 29 30 31 32 33 34 35 36 37 38 39 40 41 42 43
VCC_CORE: C118.2 R148.2 ; also on sheet 13
VDD_1V2: C114.2 R134.3 ; also on sheet 13 41
VDD_CANUART: C51.1 C54.1 C57.1 FL18.2 U12.F8(VDD_CANUART)
VDD_CORE: C55.1 C56.1 C80.1 C244.1 C247.1 C250.1 C260.1 C261.1 C262.1 C267.1 C268.1 C273.1 C277.1 C280.1 C291.1 C293.1 C295.1 C309.1 C310.1 C311.1 FL4.1 FL7.1 FL18.1 R148.3 R699.1 U12.H8(VDD_CORE) U12.J11(VDD_CORE) U12.J14(VDD_CORE) U12.K17(VDD_CORE) U12.L12(VDD_CORE) U12.L15(VDD_CORE) U12.M16(VDD_CORE) U12.N8(VDD_CORE) U12.N11(VDD_CORE) U12.N13(VDD_CORE) U12.P17(VDD_CORE) U12.R11(VDD_CORE) U12.R14(VDD_CORE) U12.U12(VDD_CORE) U12.V8(VDD_CORE) U12.V15(VDD_CORE) U12.V17(VDD_CORE)
VDD_DDR4: C81.1 C82.1 C83.1 C85.1 C282.1 C292.1 C313.1 C314.1 R134.2 U12.K9(VDDS_DDR) U12.L8(VDDS_DDR) U12.M9(VDDS_DDR_C) U12.P9(VDDS_DDR) U12.R8(VDDS_DDR) ; also on sheet 17
VDD_LDO2: C106.2 R123.3 ; also on sheet 13
VDDA1V8: C97.2 R106.2 ; also on sheet 13
VDDA_1V8: C493.1 FL3.1 FL5.1 FL6.1 FL9.1 FL13.1 FL16.1 FL19.1 R106.3 TP36.1(TP) U12.G7(VDDS_OSC0) U12.G16(VDDA_TEMP1) U12.T9(VDDA_TEMP0)
VDDA_1V8_CSIRX: C41.1 C243.1 C270.1 FL3.2 U12.W14(VDDA_1P8_CSIRX0)
VDDA_1V8_MCU: C88.1 C89.1 C90.1 FL9.2 U12.L11(VDDA_MCU)
VDDA_1V8_OLDI: C284.1 C285.1 C290.1 FL5.2 U12.W9(VDDA_1P8_OLDI0) U12.W10(VDDA_1P8_OLDI0)
VDDA_1V8_USB: C287.1 C297.1 C298.1 FL6.2 U12.Y11(VDDA_1P8_USB)
VDDA_CORE_CSI: C48.1 C275.1 C281.1 FL4.2 U12.W13(VDDA_CORE_CSIRX0)
VDDA_CORE_USB: C49.1 C283.1 C289.1 FL7.2 U12.W12(VDDA_CORE_USB)
VDDA_PLL0: C245.1 C246.1 C288.1 FL16.2 U12.U11(VDDA_PLL0)
VDDA_PLL1: C220.1 C221.1 C222.1 FL13.2 U12.U15(VDDA_PLL1)
VDDA_PLL2: C296.1 C299.1 C300.1 FL19.2 U12.L14(VDDA_PLL2)
VDDA_SYS_MON: C519.2 R108.1 R375.2 U12.H10(VMON_VSYS)
VDDR_CORE: C214.1 C215.2 C240.1 C241.1 C264.1 C271.1 C274.1 C279.1 R123.2 R699.2 TP39.1(TP) U12.J12(VDDR_CORE) U12.K16(VDDR_CORE) U12.N12(VDDR_CORE) U12.N14(VDDR_CORE) U12.P16(VDDR_CORE) U12.R12(VDDR_CORE) U12.T10(VDDR_CORE) U12.U14(VDDR_CORE)
VDDSHV_SDIO: FL14.1 ; also on sheet 13 20
CAP_VDDS0: C269.1 U12.H15(CAP_VDDS0)
CAP_VDDS1: C257.1 U12.K18(CAP_VDDS1)
CAP_VDDS2: C256.1 U12.W17(CAP_VDDS2)
CAP_VDDS3: C251.1 U12.P19(CAP_VDDS3)
CAP_VDDS4: C302.1 U12.U7(CAP_VDDS4)
CAP_VDDS5: C258.1 U12.H17(CAP_VDDS5)
CAP_VDDS6: C239.1 U12.J19(CAP_VDDS6)
CAP_VDDS_CANUART: C294.1 U12.G9(CAP_VDDS_CANUART)
CAP_VDDS_MCU: C276.1 U12.H11(CAP_VDDS_MCU)
INA_ALERT: R93.2 R110.2 R113.2 R146.2 R154.2 R290.2 R386.1 TP37.1(TP)
SOC_DVDD1V8: C36.1 C37.2 C40.1 C233.1 C252.1 C253.1 R70.3 U12.G10(VMON_1P8_SOC) U12.J18(VDDSHV6) U12.L18(VDDSHV1) U12.M19(VDDSHV1) U12.T7(VDDSHV4)
SoC_DVDD3V3: C31.1 C34.1 C42.1 C44.1 C218.1 C226.1 C249.2 C254.1 C255.1 C259.1 C265.1 C266.1 C272.1 C278.1 C286.1 R48.3 U12.F11(VDDSHV_MCU) U12.F15(VDDSHV0) U12.G12(VDDSHV_MCU) U12.G14(VDDSHV0) U12.H9(VDDSHV_CANUART) U12.K10(VMON_3P3_SOC) U12.N18(VDDSHV3) U12.P18(VDDSHV3) U12.T19(VDDSHV3) U12.U18(VDDSHV3) U12.W16(VDDSHV2) U12.W19(VDDSHV2) U12.Y13(VDDA_3P3_USB)
SOC_I2C1_SCL: U8.A1(SCL) U8.C3(A1) U16.A1(SCL) U23.A1(SCL) U23.C3(A1) U25.A1(SCL) U25.B3(A0) U36.A1(SCL) U37.A1(SCL) ; also on sheet 22 26 39 40 41 42
SOC_I2C1_SDA: U8.A2(SDA) U16.A2(SDA) U23.A2(SDA) U25.A2(SDA) U36.A2(SDA) U37.A2(SDA) ; also on sheet 22 26 39 40 41 42
SoC_VDDSHV5_SDIO: C263.1 FL14.2 U12.G17(VDDSHV5)
TEMP_DIODE_P: TP122.1(TP) U12.E7(RSVD8)
VPP_1V8: U12.J8(VPP) ; also on sheet 12
N16839912: C64.1 R78.1 U16.D3(IN+)
N16839940: C96.1 R109.1 U23.D3(IN+)
N16839975: C103.1 R125.1 U25.D3(IN+)
N17153379: R148.1 R155.2
N17153381: R148.4 R149.2
N17153415: R123.4 R147.2
N17153417: R123.1 R145.2
N17153507: R33.2 R48.1
N17153509: R37.2 R48.4
N17153511: C18.2 R37.1 U8.D1(BUS) U8.D2(IN-)
N17153515: C18.1 R33.1 U8.D3(IN+)
N17153617: R70.1 R78.2
N17153619: R70.4 R79.2
N17153623: R106.1 R109.2
N17153625: R106.4 R115.2
N17153667: R125.2 R134.4
N17153669: R124.2 R134.1
N17153681: C121.1 R155.1 U37.D3(IN+)
N17153685: C121.2 R149.1 U37.D1(BUS) U37.D2(IN-)
N17153701: C119.2 R145.1 U36.D1(BUS) U36.D2(IN-)
N17153703: C119.1 R147.1 U36.D3(IN+)
N17153749: C64.2 R79.1 U16.D1(BUS) U16.D2(IN-)
N17153787: C96.2 R115.1 U23.D1(BUS) U23.D2(IN-)
N17153799: C103.2 R124.1 U25.D1(BUS) U25.D2(IN-)
N17153878: R146.1 U36.A3(ALERT)
N17153949: R93.1 U16.A3(ALERT)
N17153951: R110.1 U23.A3(ALERT)
N17154063: R113.1 U25.A3(ALERT)
N18516151: R154.1 U37.A3(ALERT)
N18520654: R290.1 U8.A3(ALERT)

Not connected (* = marked no-connect by the designer): U8 B2(NC1)* C2(NC2)*; U16 B2(NC1)* C2(NC2)*; U23 B2(NC1)* C2(NC2)*; U25 B2(NC1)* C2(NC2)*; U36 B2(NC1)* C2(NC2)*; U37 B2(NC1)* C2(NC2)*

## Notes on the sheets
sheet 14
- CURRENT MONITORING DEVICES
- Note the supply rail name change across the shunt when optimizing
  the design (Deleting the current sense resistor)
- D-Note:-
- VDD_CORE
- SoC_DVDD1V8
- CAD Note:
  Follow Kelvin
  connection
  for Current
  Sensing  when
  using 2
  terminal
  resistors
- I2C ADDRESS: 0x40
- I2C ADDRESS: 0x45
- VDDR_CORE
- VDDA_1V8
- I2C ADDRESS: 0x4D
- I2C ADDRESS: 0x41
- SoC_DVDD3V3
- VDD_DDR4
- I2C ADDRESS: 0x4C
- I2C ADDRESS: 0x47
- D-Note :-
  RES Option to short VDD_CORE and VDDR_CORE rails when both
  are 0.85V(Both should be generated from the same source)
- INA I2C SLAVE ADDRESS
- SLAVE
  ADDRESS
  (IN HEX)
- POWER SOURCE
- SUPPLY NET
- VCC_CORE
- VDD_CORE
- 40
- VCC_3V3_SYS
- SoC_DVDD3V3
- 4C
- VCC_1V8
- SoC_DVDD1V8
- 45
- CORE SUPPLY
- ARRAY CORE SUPPLY
- Assembly
- VDDA1V8
- VDDA_1V8
- 4D
- 0.75 VDD_CORE
- 0.85 VDDR_CORE
- DNI R699 and Mount R123
- VCC1V2_DDR
- VDD_DDR4
- 47
- 0.85 VDD_CORE
- 0.85 VDDR_CORE
- DNI R123 and Mount R699
sheet 15
- D-Note :-
  Recommend implementing the voltage monitoring functionality using VMON_VSYS for
  early detection of supply failure
  It is meant to be a  power-fail indicator for the main input ( higher)  voltage rail
  that enters the PCB.  For example, 5, 12, or 24 volts.
  The error associated with this monitor would require you to set the threshold
  significantly lower than the nominal to avoid false trigger
  Refer System Power Supply Monitor Design Guidelines section of the data sheet
- SOC POWER
- D-Note :-
  Changing the core voltage is not
  allowed after the device has been
  released from reset. If you turn
  off the core supply, we expect
  you to turn off all power rails
  and ramp them down per the
  power-down sequence and wait
  untill  all supply rails decay
  below 300mv before turning on
  power again.
- D-Note :- VDD_CORE and VDDR_CORE
  are recommended to be powered by the
  same source so they ramp together
  when VDD_CORE is operating at 0.85V
- D-Note :-
  Select cap with less the 1 ohm ESR
  Ensure the PCB loop inductance is < 2.5 nH
  Select 0201 package or smallest possible package
  Refer SoC Data sheet
- R-Note
  Connecting 1.8V supply source
  directly to VPP continuously is
  not allowed
- Internal purpose only
- R-Note:- Reserved pin
  Leave unconnected
- D-Note :-
  Refer pin connectivity table of the SOC data sheet for connecting the USB IO,
  analog and core supplies when USB interface is not used.
  It is acceptable to have the supplies connected and all the USB pins left
  unconnected provided the USB driver is not initialized any time and the USB
  calibration procedure does not happen.
  Grounding the USB supplies as per pin connectivity requirements when not used
  saves power when low power is a critical requirement.
- D-Note :-
  Refer Pin connectivity requirements to
  connect the CSI0 supplies (analog and core)
  when CSI0 interface is not used
  Ferrite and Bulk Caps are optional when CSI0
  is not used and Boundary scan functionality
  is required
- 1.8V ANALOG SUPPLIES
- CORE SUPPLIES
- 3.3V/1.8V MMC1 SUPPLY
- D-Note :-
  Common SOC LVCMOS IO interface guidelines
  1. Most of the SOC IOs are not fail-safe. No input should be applied before supply ramps.
  2. SOC LVCMOS inputs have minimum slew rate requirements specified
  3. SOC IO buffers are off during Reset. A pull is required near to the attached device being
  driven by the SOC IOs
  4. Any SOC IO that has a trace connected  and not being actively driven needs a parallel
  pull. When adding pull is not feasible, ensure the traces are routed away from noisy signals
- D-Note :-
  Add a bulk cap 1 uF  to minimize
  resonance
- D-Note :-
  A Trace connected to SOC  is effectively an antenna that will pick up noise.
  A potential will be generated on the signal when noise couples into the
  antenna.  This potential will be largest on the highest impedance end of the
  signal.
  By placing a pull-up or pull-down near the SoC pin, we force the highest
  potential to the open-circuit end of the signal rather than the SoC end of the
  signal.
sheet 16
- SOC POWER SUPPLIES - DECAPS
- CAD Note:- Place 0.1 uF caps near to SoC pins
- CAD Note:- Place 0.1 uF caps near to SoC pins
- CAD Note:- Place 0.1 uF caps near to SoC pins
- CAD Note:- Place 0.1 uF caps near to SoC pins
- CAD Note:- Place 0.1 uF caps near to SoC pins
- SOC VSS
